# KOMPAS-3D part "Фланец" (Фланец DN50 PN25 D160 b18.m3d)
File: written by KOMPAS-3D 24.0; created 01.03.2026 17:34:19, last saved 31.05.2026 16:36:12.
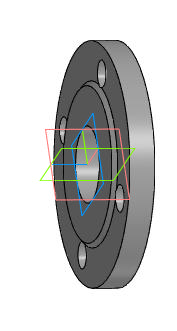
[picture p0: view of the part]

Document properties: Автор: R2D2; Полное имя файла: E:\Работа\Зайцев\GVWR2121M-2W-F-ОСТ Задвижка клиновая 30с964нж DN.ru Ду50-300 Ру25\исходные материалы\DN50\Фланец DN50 PN25 D160 b18.m3d

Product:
- Part/product: Фланец
    Масса: 2.444901
    additional columns: Типовые
- Part/product: Фланец  | designation 01
    Масса: 2.168144
    additional columns: Типовые

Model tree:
1. Эскиз:2
2. Элемент вращения:1
     Угол 1 = 360
3. Эскиз:3  (with: Грань.Элемент вращения:1)
4. Элемент выдавливания:2
     Расстояние 1 = 3; Расстояние 2 = 17
5. Массив по концентрической сетке:1  (with: Элемент выдавливания:2, Эскиз:3, Грань.Элемент вращения:1)  (4 pattern instances)
     Шаг 2 = 360

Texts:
  Линейный размер с обрывом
